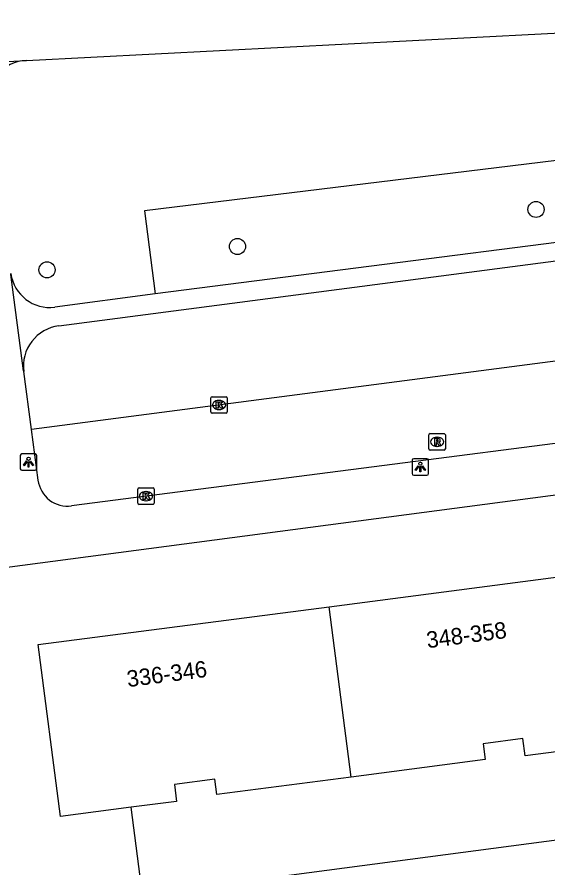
# Model space of a CAD drawing. Extents: x 161084 to 161928, y 385355 to 386522.
# Drawn here: x 161242.8 to 161275.1, y 385538 to 385589.7 of the extents above; entities that cross this region are included whole.
import ezdxf

# ---------------------------------------------------------------- set-up
doc = ezdxf.new("R2010")
doc.units = 0
for name, color, linetype in [('IMGEO_Boom', 7, 'Continuous'), ('IMGEO_Groenvoorziening', 7, 'Continuous'), ('IMGEO_Kolk', 7, 'Continuous'), ('IMGEO_Lichtpunt', 7, 'Continuous'), ('IMGEO_Pand', 7, 'Continuous'), ('IMGEO_Pand_nummerreeks', 7, 'Continuous'), ('IMGEO_Rijbaan_lokaal_open', 7, 'Continuous'), ('IMGEO_Rioolput', 7, 'Continuous'), ('IMGEO_Voetpad_open', 7, 'Continuous')]:
    doc.layers.add(name, color=color, linetype=linetype)

msp = doc.modelspace()

# ---------------------------------------------------------------- linework, layer by layer
at = {"layer": 'IMGEO_Boom'}
for centre in [(161274.383, 385577.946), (161256.209, 385575.695), (161244.614, 385574.274)]:
    msp.add_circle(centre, 0.489, dxfattribs=at)
at = {"layer": 'IMGEO_Groenvoorziening'}
msp.add_lwpolyline([(161290.538, 385577.838), (161289.91, 385582.669), (161250.553, 385577.86), (161251.206, 385572.808)], dxfattribs=at)
at = {"layer": 'IMGEO_Kolk'}
for p, q in [((161254.589, 385565.63), (161254.589, 385566.482)), ((161254.664, 385566.556), (161255.516, 385566.556)), ((161255.077, 385566.336), (161255.102, 385566.336)), ((161255.59, 385566.482), (161255.59, 385565.63)), ((161255.516, 385565.556), (161254.664, 385565.556)), ((161255.1, 385565.776), (161255.075, 385565.776)), ((161250.14, 385560.087), (161250.14, 385560.939)), ((161250.215, 385561.013), (161251.067, 385561.013)), ((161250.628, 385560.793), (161250.653, 385560.793)), ((161251.141, 385560.939), (161251.141, 385560.087)), ((161250.651, 385560.233), (161250.626, 385560.233)), ((161251.067, 385560.013), (161250.215, 385560.013))]:
    msp.add_line(p, q, dxfattribs=at)
for points in [[(161254.589, 385565.63), (161254.589, 385566.482)], [(161254.664, 385566.556), (161255.516, 385566.556)], [(161255.59, 385566.482), (161255.59, 385565.63)], [(161254.91, 385566.256), (161255.033, 385566.256), (161255.033, 385566.105), (161255.163, 385566.256), (161255.327, 385566.256), (161255.181, 385566.105), (161255.334, 385565.856), (161255.182, 385565.856), (161255.097, 385566.02), (161255.033, 385565.953), (161255.033, 385565.856), (161254.91, 385565.856), (161254.91, 385566.256)], [(161255.516, 385565.556), (161254.664, 385565.556)], [(161250.14, 385560.087), (161250.14, 385560.939)], [(161250.215, 385561.013), (161251.067, 385561.013)], [(161250.461, 385560.713), (161250.584, 385560.713), (161250.584, 385560.562), (161250.714, 385560.713), (161250.878, 385560.713), (161250.732, 385560.562), (161250.885, 385560.313), (161250.733, 385560.313), (161250.648, 385560.477), (161250.584, 385560.41), (161250.584, 385560.313), (161250.461, 385560.313), (161250.461, 385560.713)], [(161251.141, 385560.939), (161251.141, 385560.087)], [(161251.067, 385560.013), (161250.215, 385560.013)]]:
    msp.add_lwpolyline(points, dxfattribs=at)
for centre, start, end in [((161254.666, 385566.48), 91.552, 178.448), ((161254.666, 385566.48), 91.552, 178.448), ((161255.514, 385566.48), 1.552, 88.448), ((161255.514, 385566.48), 1.552, 88.448), ((161254.666, 385565.632), 181.552, 268.448), ((161254.666, 385565.632), 181.552, 268.448), ((161255.514, 385565.632), 271.552, 358.448), ((161255.514, 385565.632), 271.552, 358.448), ((161250.217, 385560.937), 91.552, 178.448), ((161250.217, 385560.937), 91.552, 178.448), ((161251.065, 385560.937), 1.552, 88.448), ((161251.065, 385560.937), 1.552, 88.448), ((161250.217, 385560.089), 181.552, 268.448), ((161250.217, 385560.089), 181.552, 268.448), ((161251.065, 385560.089), 271.552, 358.448), ((161251.065, 385560.089), 271.552, 358.448)]:
    msp.add_arc(centre, 0.0765, start, end, dxfattribs=at)
for centre, major_axis, ratio, start_param, end_param in [((161255.076, 385566.056), (-0.387, 0.002), 0.722429, 4.712389, 7.853982), ((161255.101, 385566.056), (-0.39, 0.002), 0.717154, 1.570796, 4.712389), ((161250.627, 385560.513), (-0.387, 0.002), 0.722429, 4.712389, 7.853982), ((161250.652, 385560.513), (-0.39, 0.002), 0.717154, 1.570796, 4.712389)]:
    msp.add_ellipse(centre, major_axis=major_axis, ratio=ratio, start_param=start_param, end_param=end_param, dxfattribs=at)
at = {"layer": 'IMGEO_Lichtpunt'}
for p, q in [((161242.99, 385562.985), (161242.99, 385562.178)), ((161242.99, 385562.985), (161242.99, 385562.178)), ((161243.892, 385563.08), (161243.084, 385563.08)), ((161243.892, 385563.08), (161243.084, 385563.08)), ((161243.986, 385562.178), (161243.986, 385562.985)), ((161243.986, 385562.178), (161243.986, 385562.985)), ((161267.744, 385562.785), (161266.936, 385562.785)), ((161267.744, 385562.785), (161266.936, 385562.785)), ((161266.842, 385562.69), (161266.842, 385561.883)), ((161266.842, 385562.69), (161266.842, 385561.883)), ((161267.838, 385561.883), (161267.838, 385562.69)), ((161267.838, 385561.883), (161267.838, 385562.69)), ((161243.084, 385562.084), (161243.892, 385562.084)), ((161243.084, 385562.084), (161243.892, 385562.084)), ((161266.936, 385561.789), (161267.744, 385561.789)), ((161266.936, 385561.789), (161267.744, 385561.789))]:
    msp.add_line(p, q, dxfattribs=at)
for points in [[(161243.364, 385562.649), (161243.403, 385562.621), (161243.215, 385562.359), (161243.177, 385562.386), (161243.364, 385562.649)], [(161243.466, 385562.601), (161243.513, 385562.601), (161243.513, 385562.279), (161243.466, 385562.279), (161243.466, 385562.601)], [(161243.576, 385562.621), (161243.614, 385562.648), (161243.801, 385562.386), (161243.762, 385562.358), (161243.576, 385562.621)], [(161267.216, 385562.354), (161267.255, 385562.326), (161267.067, 385562.064), (161267.029, 385562.091), (161267.216, 385562.354)], [(161267.318, 385562.306), (161267.365, 385562.306), (161267.365, 385561.984), (161267.318, 385561.984), (161267.318, 385562.306)], [(161267.428, 385562.326), (161267.466, 385562.353), (161267.653, 385562.091), (161267.614, 385562.063), (161267.428, 385562.326)]]:
    msp.add_lwpolyline(points, dxfattribs=at)
for centre in [(161243.489, 385562.783), (161267.341, 385562.488)]:
    msp.add_circle(centre, 0.0994, dxfattribs=at)
for centre, start, end in [((161243.084, 385562.985), 90, 180), ((161243.084, 385562.985), 90, 180), ((161243.892, 385562.985), 0, 90), ((161243.892, 385562.985), 0, 90), ((161266.936, 385562.69), 90, 180), ((161266.936, 385562.69), 90, 180), ((161267.744, 385562.69), 0, 90), ((161267.744, 385562.69), 0, 90), ((161243.084, 385562.178), 180, 270), ((161243.084, 385562.178), 180, 270), ((161243.892, 385562.178), 270, 0), ((161243.892, 385562.178), 270, 360), ((161266.936, 385561.883), 180, 270), ((161266.936, 385561.883), 180, 270), ((161267.744, 385561.883), 270, 0), ((161267.744, 385561.883), 270, 360)]:
    msp.add_arc(centre, 0.0946, start, end, dxfattribs=at)
at = {"layer": 'IMGEO_Pand'}
for points in [[(161261.782, 385553.789), (161280.559, 385556.226)], [(161249.742, 385541.592), (161245.441, 385541.034), (161244.084, 385551.492), (161261.782, 385553.789)], [(161263.127, 385543.431), (161261.782, 385553.789)], [(161281.916, 385545.773), (161273.728, 385544.71), (161273.59, 385545.772), (161271.17, 385545.458), (161271.296, 385544.491), (161263.127, 385543.431)], [(161263.127, 385543.431), (161254.957, 385542.37), (161254.837, 385543.295), (161252.37, 385542.975), (161252.503, 385541.951), (161249.742, 385541.592)]]:
    msp.add_lwpolyline(points, dxfattribs=at)
at = {"layer": 'IMGEO_Rijbaan_lokaal_open'}
for points in [[(161295.147, 385571.265), (161243.66, 385564.569)], [(161296.49, 385566.403), (161246.111, 385559.915)], [(161244.066, 385561.483), (161243.66, 385564.569)]]:
    msp.add_lwpolyline(points, dxfattribs=at)
msp.add_arc((161245.872, 385561.721), 1.822, 187.504, 277.5377, dxfattribs=at)
at = {"layer": 'IMGEO_Rioolput'}
for p, q in [((161267.937, 385564.312), (161268.789, 385564.312)), ((161267.862, 385563.386), (161267.862, 385564.238)), ((161268.35, 385564.092), (161268.375, 385564.092)), ((161268.863, 385564.238), (161268.863, 385563.386)), ((161268.789, 385563.312), (161267.937, 385563.312)), ((161268.373, 385563.532), (161268.348, 385563.532))]:
    msp.add_line(p, q, dxfattribs=at)
for points in [[(161267.937, 385564.312), (161268.789, 385564.312)], [(161267.862, 385563.386), (161267.862, 385564.238)], [(161268.451, 385564.01), (161268.199, 385564.012), (161268.199, 385563.612)], [(161268.199, 385563.612), (161268.323, 385563.612), (161268.323, 385563.774), (161268.334, 385563.774)], [(161268.377, 385563.931), (161268.323, 385563.931), (161268.323, 385563.85)], [(161268.323, 385563.85), (161268.375, 385563.85)], [(161268.381, 385563.745), (161268.452, 385563.612), (161268.592, 385563.612), (161268.527, 385563.738)], [(161268.863, 385564.238), (161268.863, 385563.386)], [(161268.789, 385563.312), (161267.937, 385563.312)]]:
    msp.add_lwpolyline(points, dxfattribs=at)
for centre, radius, start, end in [((161267.939, 385564.236), 0.0765, 91.552, 178.448), ((161267.939, 385564.236), 0.0765, 91.552, 178.448), ((161268.787, 385564.236), 0.0765, 1.552, 88.448), ((161268.787, 385564.236), 0.0765, 1.552, 88.448), ((161268.333, 385563.721), 0.0533, 26.0293, 88.6989), ((161268.359, 385564.039), 0.19, 274.7715, 282.9687), ((161268.383, 385563.835), 0.0964, 77.0061, 93.1865), ((161268.397, 385563.892), 0.0378, 276.6634, 79.6772), ((161268.45, 385563.9), 0.109, 350.3612, 89.416), ((161268.448, 385563.9), 0.112, 277.5842, 350.9817), ((161268.432, 385563.685), 0.108, 29.5134, 73.7905), ((161267.939, 385563.388), 0.0765, 181.552, 268.448), ((161267.939, 385563.388), 0.0765, 181.552, 268.448), ((161268.787, 385563.388), 0.0765, 271.552, 358.448), ((161268.787, 385563.388), 0.0765, 271.552, 358.448)]:
    msp.add_arc(centre, radius, start, end, dxfattribs=at)
for centre, major_axis, ratio, start_param, end_param in [((161268.349, 385563.812), (-0.387, 0.002), 0.722429, 4.712389, 7.853982), ((161268.374, 385563.812), (-0.39, 0.002), 0.717154, 1.570796, 4.712389)]:
    msp.add_ellipse(centre, major_axis=major_axis, ratio=ratio, start_param=start_param, end_param=end_param, dxfattribs=at)
at = {"layer": 'IMGEO_Voetpad_open'}
for points in [[(161243.359, 385587.013), (161294.279, 385589.65)], [(161237.271, 385586.682), (161243.336, 385587.014), (161243.359, 385587.013)], [(161290.538, 385577.838), (161251.206, 385572.808)], [(161245.338, 385570.87), (161290.484, 385576.758)], [(161243.197, 385568.084), (161243.18, 385568.142), (161242.418, 385573.984), (161242.417, 385574.055)], [(161251.206, 385572.808), (161245.095, 385572.003)], [(161243.66, 385564.569), (161243.197, 385568.084)], [(161240.171, 385555.923), (161297.57, 385563.486)], [(161300.38, 385542.861), (161250.436, 385536.264)], [(161250.436, 385536.264), (161249.742, 385541.592)]]:
    msp.add_lwpolyline(points, dxfattribs=at)
for centre, radius, start, end in [((161243.48, 385584.574), 2.442, 92.8469, 188.9118), ((161244.784, 385574.371), 2.388, 187.6029, 277.4753), ((161245.658, 385568.408), 2.483, 97.4163, 187.5002)]:
    msp.add_arc(centre, radius, start, end, dxfattribs=at)

# ---------------------------------------------------------------- texts
at = {"layer": 'IMGEO_Pand_nummerreeks'}
for s, rotation, p in [('348-358', 7.3956, (161267.779, 385551.26)), ('336-346', 7.3969, (161249.538, 385548.892))]:
    msp.add_text(s, height=1, rotation=rotation, dxfattribs=at).set_placement(p)

doc.saveas('drawing.dxf')
